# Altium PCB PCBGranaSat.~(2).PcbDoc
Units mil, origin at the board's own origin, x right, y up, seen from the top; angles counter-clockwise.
Board outline 6000 x 4000 mil, 2 copper layers (Top Layer, Bottom Layer); 6 components, 23 nets, 108 pads, 0 vias.
Unrouted connection lines stored in the file: 22.
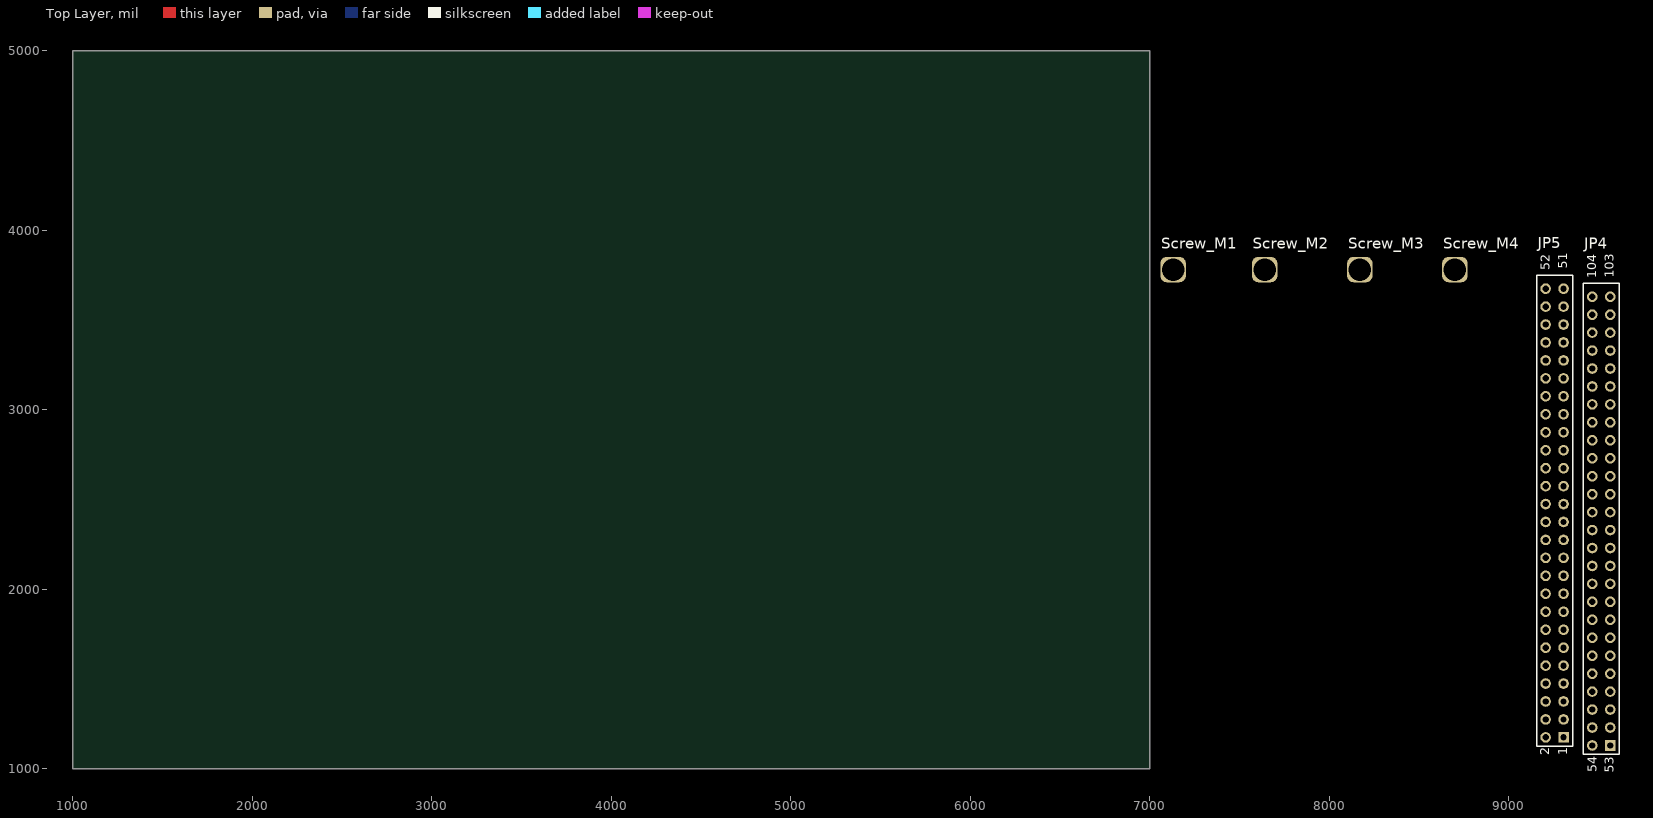
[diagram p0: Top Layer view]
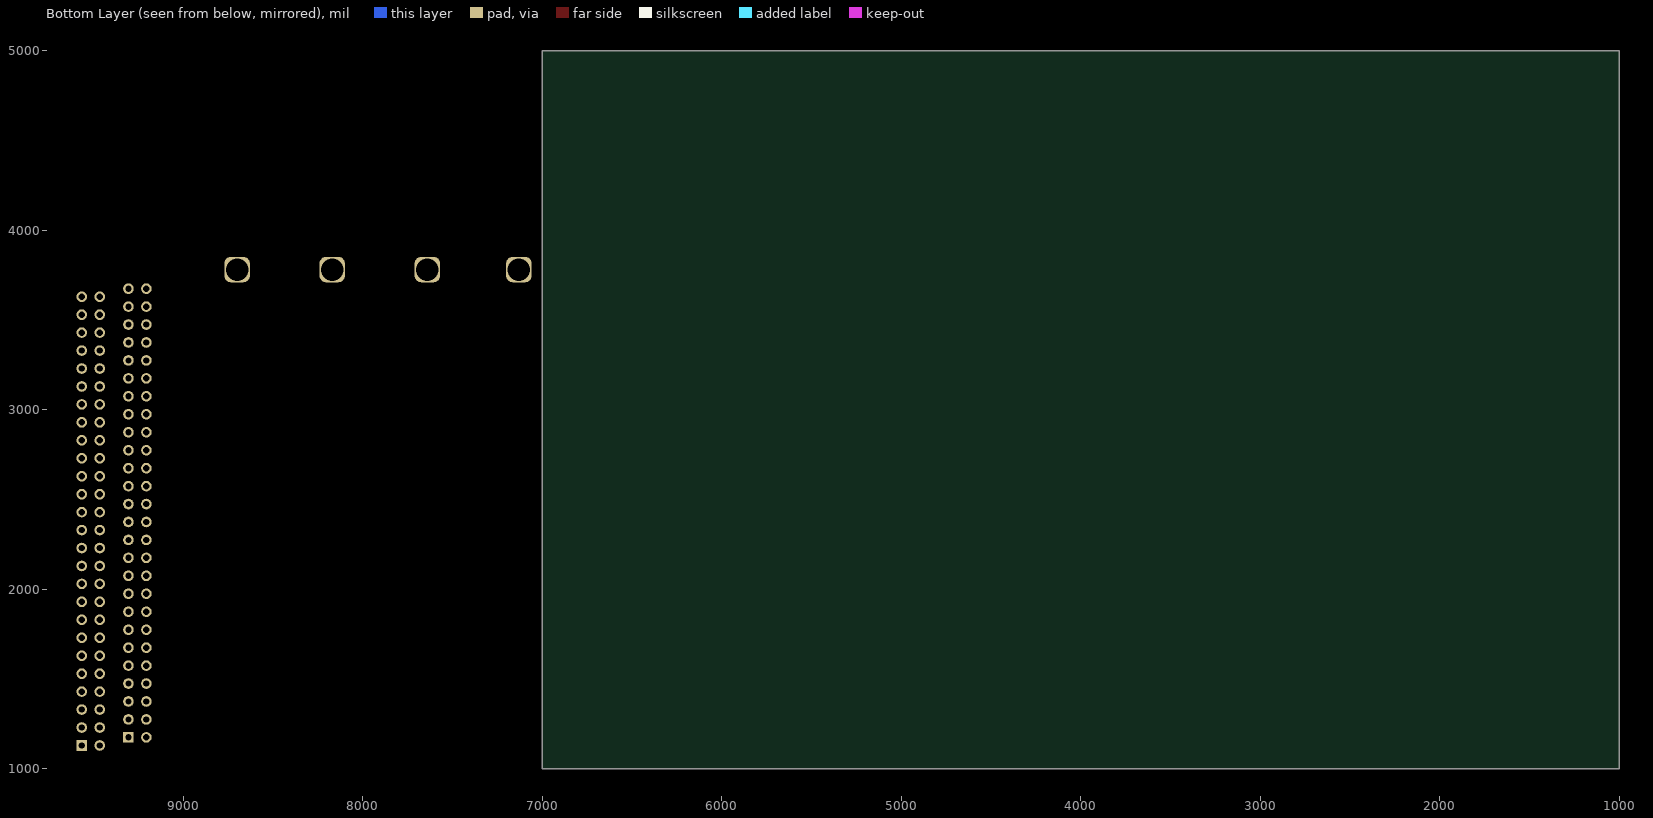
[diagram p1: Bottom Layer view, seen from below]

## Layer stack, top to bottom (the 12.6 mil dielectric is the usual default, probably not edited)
Top Solder: solder mask 0.4, Solder Resist, Dk 3.5
Top Layer: signal copper 1.4
Dielectric 1: dielectric 12.6, FR-4, Dk 4.8
Bottom Layer: signal copper 1.4
Bottom Solder: solder mask 0.4, Solder Resist, Dk 3.5

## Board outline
1000,1000 7000,1000 7000,5000 1000,5000

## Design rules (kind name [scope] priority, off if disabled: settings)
Clearance [All] p1: gap=10
PolygonConnect [All] p1: connectstyle=Relief reliefconductorwidth=10 reliefentries=4 polygonreliefangle="90 Angle" airgapwidth=10
RoomDefinition Sheet1 [InComponentClass('Sheet1')] p1: confinementstyle=ConfineIn formatcopy=TRUE lockcomponents=FALSE outline 7045,960 9625,960 9625,3975 7045,3975
RoutingVias [All] p1: holewidth=28 width=50 viastyle="Through Hole" minholewidth=28 minwidth=50 maxholewidth=28 maxwidth=50
SolderMaskExpansion [All] p1: expansion=4
Width [All] p1: maxlimit=10 minlimit=10 preferedwidth=10
30 further rules are at their usual default settings.

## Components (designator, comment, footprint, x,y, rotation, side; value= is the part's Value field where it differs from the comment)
JP4 "ESQ-126-39-G-D_53-104" ESQ-126-39-G-D_53_104 9565,1130 r90 top
JP5 "ESQ-126-39-G-D" ESQ-126-39-G-D 9305,1175 r90 top
Screw_M1 "SC1" Screw_M3 8210,945 r90 top
Screw_M2 "SC1" Screw_M3 8720,945 r90 top
Screw_M3 "SC1" Screw_M3 9250,945 r90 top
Screw_M4 "SC1" Screw_M3 9780,945 r90 top

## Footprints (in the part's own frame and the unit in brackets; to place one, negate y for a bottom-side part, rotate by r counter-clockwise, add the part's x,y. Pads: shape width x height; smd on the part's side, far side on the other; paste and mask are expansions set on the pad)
ESQ-126-39-G-D [mm] "Cubesat Connector; Header; 26x2 Position"
  rect 1.5x1.5 hole 0.9: 1(0,0)
  round 1.5 hole 0.9: 2(0,2.54) 3(2.54,0) 4(2.54,2.54) 5(5.08,0) 6(5.08,2.54) 7(7.62,0) 8(7.62,2.54) 9(10.16,0) 10(10.16,2.54) 11(12.7,0) 12(12.7,2.54) 13(15.24,0) 14(15.24,2.54) 15(17.78,0) 16(17.78,2.54) 17(20.32,0) 18(20.32,2.54) 19(22.86,0) 20(22.86,2.54) 21(25.4,0) 22(25.4,2.54) 23(27.94,0) 24(27.94,2.54) 25(30.48,0) 26(30.48,2.54) 27(33.02,0) 28(33.02,2.54) 29(35.56,0) 30(35.56,2.54) 31(38.1,0) 32(38.1,2.54) 33(40.64,0) 34(40.64,2.54) 35(43.18,0) 36(43.18,2.54) 37(45.72,0) 38(45.72,2.54) 39(48.26,0) 40(48.26,2.54) 41(50.8,0) 42(50.8,2.54) 43(53.34,0) 44(53.34,2.54) 45(55.88,0) 46(55.88,2.54) 47(58.42,0) 48(58.42,2.54) 49(60.96,0) 50(60.96,2.54) 51(63.5,0) 52(63.5,2.54)
  silkscreen extent -1.27,-1.27 65.38,3.81, body extent -1.3,-1.3 65.25,3.78, height 10.51
ESQ-126-39-G-D_53_104 [mm] "Cubesat Connector; Header; 26x2 Position"
  rect 1.5x1.5 hole 0.9: 53(0,0)
  round 1.5 hole 0.9: 54(0,2.54) 55(2.54,0) 56(2.54,2.54) 57(5.08,0) 58(5.08,2.54) 59(7.62,0) 60(7.62,2.54) 61(10.16,0) 62(10.16,2.54) 63(12.7,0) 64(12.7,2.54) 65(15.24,0) 66(15.24,2.54) 67(17.78,0) 68(17.78,2.54) 69(20.32,0) 70(20.32,2.54) 71(22.86,0) 72(22.86,2.54) 73(25.4,0) 74(25.4,2.54) 75(27.94,0) 76(27.94,2.54) 77(30.48,0) 78(30.48,2.54) 79(33.02,0) 80(33.02,2.54) 81(35.56,0) 82(35.56,2.54) 83(38.1,0) 84(38.1,2.54) 85(40.64,0) 86(40.64,2.54) 87(43.18,0) 88(43.18,2.54) 89(45.72,0) 90(45.72,2.54) 91(48.26,0) 92(48.26,2.54) 93(50.8,0) 94(50.8,2.54) 95(53.34,0) 96(53.34,2.54) 97(55.88,0) 98(55.88,2.54) 99(58.42,0) 100(58.42,2.54) 101(60.96,0) 102(60.96,2.54) 103(63.5,0) 104(63.5,2.54)
  silkscreen extent -1.27,-1.27 65.38,3.81, body extent -1.3,-1.3 65.25,3.78, height 10.51
Screw_M3 [mm] "Main CubeSAT bus M3 screw"
  rrect50% 3.6x3.6 hole 3.2: 1(72.04,27.44)

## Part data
JP4 JP5: "Cubesat Header Connector"
Screw_M1 Screw_M2 Screw_M3 Screw_M4: library part Screw_M3, "Main CubeSAT bus"

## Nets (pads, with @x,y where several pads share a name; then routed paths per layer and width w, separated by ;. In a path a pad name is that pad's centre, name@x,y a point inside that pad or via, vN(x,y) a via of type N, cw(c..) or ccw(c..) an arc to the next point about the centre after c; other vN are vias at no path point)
+5V: JP4.77 JP4.78
"BUS3 GPIO0": JP4.64
"BUS3 GPIO1": JP4.63
"BUS3 GPIO2": JP4.66
"BUS3 GPIO3": JP4.65
"BUS4 CLK": JP5.35
"BUS4 CS": JP5.40
"BUS4 GPIO0": JP5.7
"BUS4 GPIO1": JP5.6
"BUS4 GPIO2": JP5.9
"BUS4 MISO": JP5.37
"BUS4 MOSI": JP5.39
"BUS4 RST": JP5.11
BUS6: JP4.57
"EN R PA BEACON": JP5.8
GND: JP4.53 JP4.54 JP4.55 JP4.56 JP4.81 JP4.82 JP4.83 JP4.84 JP5.1 JP5.2 JP5.3 JP5.4 JP5.29 JP5.30 JP5.31 JP5.32
"R ANT": JP4.87 JP4.88
"R EPS/BEACON": JP4.80
"R PA BEACON": JP5.51 JP5.52
"R PA TRANSC": JP5.49 JP5.50
SCLC: JP5.43
SDAC: JP5.41
SGND: Screw_M1.1 Screw_M2.1 Screw_M3.1 Screw_M4.1
pads on no net: JP4.58 JP4.59 JP4.60 JP4.61 JP4.62 JP4.67 JP4.68 JP4.69 JP4.70 JP4.71 JP4.72 JP4.73 JP4.74 JP4.75 JP4.76 JP4.79 JP4.85 JP4.86 JP4.89 JP4.90 JP4.91 JP4.92 JP4.93 JP4.94 JP4.95 JP4.96 JP4.97 JP4.98 JP4.99 JP4.100 JP4.101 JP4.102 JP4.103 JP4.104 JP5.5 JP5.10 JP5.12 JP5.13 JP5.14 JP5.15 JP5.16 JP5.17 JP5.18 JP5.19 JP5.20 JP5.21 JP5.22 JP5.23 JP5.24 JP5.25 JP5.26 JP5.27 JP5.28 JP5.33 JP5.34 JP5.36 JP5.38 JP5.42 JP5.44 JP5.45 JP5.46 JP5.47 JP5.48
